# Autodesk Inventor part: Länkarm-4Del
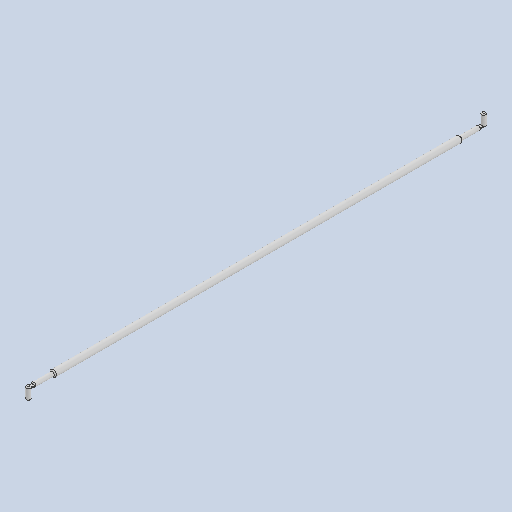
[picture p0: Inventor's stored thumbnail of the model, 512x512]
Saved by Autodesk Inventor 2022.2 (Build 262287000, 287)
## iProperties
Created: 2022-03
Part Number: Länkarm-4Del
Material: Generic
Document SubType Name: Modeling
Designer: cl
Density: 1 g/cm^3
Appearance: Default
Author: cl
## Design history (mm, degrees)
sketch "Sketch1"
  geometry: L1 (0, 0)-(0, -2066.69); L2 (0, 0)-(-10, 0); L3 (-10, 0)-(-10, -90); L4 (-10, -90)-(-15, -90); L5 (-15, -90)-(-15, -1976.69); L6 (0, -2066.69)-(-10, -2066.69); L7 (-10, -2066.69)-(-10, -1976.69); L8 (-10, -1976.69)-(-15, -1976.69); 1 further point
  constraints: 16 end point, 5 perpendicular, 2 horizontal, 1 midpoint, 1 vertical
  dimensions: "d0" = 2066.69 distance of L1.start L1.end (computed from BladBredd); "d1" = 20 diameter of L3 L1; "d2" = 5 distance between parallel lines of L3 L5; "d3" = 90 distance of L2.end L3.end; "d4" = 20 diameter of L7 L1; "d5" = 90 vertical distance of point (-5, -2066.69) L5.end
revolve "Revolution1" sketch "Sketch1" stored, may be unused: angle "d6" = 90 deg
fillet "Fillet1" dims "d7" = 5
workplane "Work Plane1"
sketch "Sketch2"
  geometry: L1 (10, 0)-(-10, 0) reference; L2 (7.5, 0)-(-7.5, 0); L3 (-7.5, 0)-(-7.5, 20); L4 (-7.5, 20)-(7.5, 20); L5 (7.5, 20)-(7.5, 0); L6 (10, -90)-(10, 0) reference; L7 (10, -2066.69)-(-10, -2066.69) reference; L8 (7.5, -2066.69)-(-7.5, -2066.69); L9 (-7.5, -2066.69)-(-7.5, -2086.69); L10 (-7.5, -2086.69)-(7.5, -2086.69); L11 (7.5, -2086.69)-(7.5, -2066.69); 3 further points
  constraints: 16 end point, 4 parallel, 2 horizontal, 2 perpendicular, 2 point on line, 1 collinear
  dimensions: "d9" = 2.5 distance between parallel lines of L5 L6; "d10" = 15 distance of L3.end L4.end; "d11" = 20 distance of L2.end L3.end; "d12" = 20 distance of L8.end L9.end; "d13" = 15 distance of L9.end L10.end
extrude "Extrusion1" join sketch "Sketch2" distance "d14" = 4; taper "d15" = 0 deg
sketch "Sketch3"
  geometry: L1 (7.5, 20)-(-7.5, 20) reference; L2 (-7.5, -2086.69)-(7.5, -2086.69) reference; C1 r 10 at (0, 20); C2 r 10 at (0, -2086.69); 1 further point
  constraints: 2 centre point, 2 midpoint
  dimensions: "d16" = 20 diameter of C1; "d17" = 20 diameter of C2
extrude "Extrusion2" join sketch "Sketch3" distance "d18" = 8; taper "d20" = 0 deg; dims "d19" = 48, "d21" = 0
extrude "Extrusion3" join sketch "Sketch3" distance "d22" = 50; taper "d24" = 0 deg; dims "d23" = 6, "d25" = 0
fillet "Fillet2" dims "d26" = 5
body "Solid1"
other parameters: "BladBredd" = 987.5, "Fönsterhöjd" = 862, "Blad2" = 1012.5, "Blad3" = 0, "Blad4" = 0, "Blad5" = 1012.5, "Blad6" = 2025, "MGJ12Djup" = 0, "MGJ12Bredd" = 0, "MGJ2Djup" = 0, "MGJ2Bredd" = 5012.5, "MGJ56Djup" = 0, "MGJ56Bredd" = 0, "MGJ23Djup" = 48, "MGJ45Djup" = 48, "GarageRegel5" = 0, "GarageRegel6" = 0, "Styrrulle2Djup" = 0, "FönsterhöjdStyrning" = 862, "FönsterKarm" = 54, "AndraGlasraden" = 0, "BrösthöjdStyrning2" = 0.0001, "InfälldGångDörr" = 0, "Infälldstyr" = 1012.5, "EnDelGångDörr" = 0, "VinkelJärnStyrSkena" = 1456.25, "d8" = -2
